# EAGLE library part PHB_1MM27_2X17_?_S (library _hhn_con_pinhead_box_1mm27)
Pin Header Box-Type, 1.27mm/0.5"/50mil Pitch, 2x17 Circuits, single gates in schematic Note: see library description for an important note about THT-version
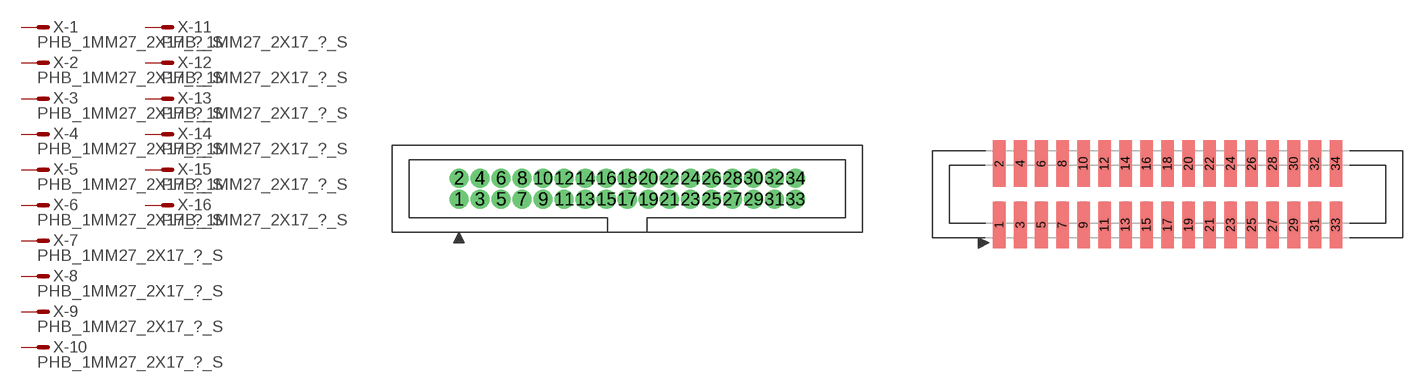
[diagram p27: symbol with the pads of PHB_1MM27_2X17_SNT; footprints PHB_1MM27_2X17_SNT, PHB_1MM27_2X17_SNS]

Designator prefix X; gates -1=M -2=M -3=M -4=M -5=M -6=M -7=M -8=M -9=M -10=M -11=M -12=M -13=M -14=M -15=M -16=M -17=M -18=M -19=M -20=M -21=M -22=M -23=M -24=M -25=M -26=M -27=M -28=M -29=M -30=M -31=M -32=M -33=M -34=M

## PHB_1MM27_2X17_SNT_S  [PHB_1MM27_2X17_SNT]
1  -1:S  pas
2  -2:S  pas
3  -3:S  pas
4  -4:S  pas
5  -5:S  pas
6  -6:S  pas
7  -7:S  pas
8  -8:S  pas
9  -9:S  pas
10  -10:S  pas
11  -11:S  pas
12  -12:S  pas
13  -13:S  pas
14  -14:S  pas
15  -15:S  pas
16  -16:S  pas
17  -17:S  pas
18  -18:S  pas
19  -19:S  pas
20  -20:S  pas
21  -21:S  pas
22  -22:S  pas
23  -23:S  pas
24  -24:S  pas
25  -25:S  pas
26  -26:S  pas
27  -27:S  pas
28  -28:S  pas
29  -29:S  pas
30  -30:S  pas
31  -31:S  pas
32  -32:S  pas
33  -33:S  pas
34  -34:S  pas

## PHB_1MM27_2X17_SNS_S  [PHB_1MM27_2X17_SNS]
Pads as for PHB_1MM27_2X17_SNT

## Footprint PHB_1MM27_2X17_SNT (pad centres in mm)
Pin Header Box-Type, 1.27mm Pitch, 2x17 circuits, Straight, No Locking, THT Important Note: Diameter in this lbr is set to a specific value (NOT 'auto' = 0), this is ignored by actual eagle versions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
drill 0.65 pad 1 round: 1 -10.16,-0.635; 2 -10.16,0.635; 3 -8.89,-0.635; 4 -8.89,0.635; 5 -7.62,-0.635; 6 -7.62,0.635; 7 -6.35,-0.635; 8 -6.35,0.635; 9 -5.08,-0.635; 10 -5.08,0.635; 11 -3.81,-0.635; 12 -3.81,0.635; 13 -2.54,-0.635; 14 -2.54,0.635; 15 -1.27,-0.635; 16 -1.27,0.635; 17 0,-0.635; 18 0,0.635; 19 1.27,-0.635; 20 1.27,0.635; 21 2.54,-0.635; 22 2.54,0.635; 23 3.81,-0.635; 24 3.81,0.635; 25 5.08,-0.635; 26 5.08,0.635; 27 6.35,-0.635; 28 6.35,0.635; 29 7.62,-0.635; 30 7.62,0.635; 31 8.89,-0.635; 32 8.89,0.635; 33 10.16,-0.635; 34 10.16,0.635

## Footprint PHB_1MM27_2X17_SNS (pad centres in mm)
Pin Header Box-Type, 1.27mm Pitch, 2x17 circuits, Straight, No Locking, SMT
smd 0.76 x 2.8: 1 -10.16,-1.85; 2 -10.16,1.85; 3 -8.89,-1.85; 4 -8.89,1.85; 5 -7.62,-1.85; 6 -7.62,1.85; 7 -6.35,-1.85; 8 -6.35,1.85; 9 -5.08,-1.85; 10 -5.08,1.85; 11 -3.81,-1.85; 12 -3.81,1.85; 13 -2.54,-1.85; 14 -2.54,1.85; 15 -1.27,-1.85; 16 -1.27,1.85; 17 0,-1.85; 18 0,1.85; 19 1.27,-1.85; 20 1.27,1.85; 21 2.54,-1.85; 22 2.54,1.85; 23 3.81,-1.85; 24 3.81,1.85; 25 5.08,-1.85; 26 5.08,1.85; 27 6.35,-1.85; 28 6.35,1.85; 29 7.62,-1.85; 30 7.62,1.85; 31 8.89,-1.85; 32 8.89,1.85; 33 10.16,-1.85; 34 10.16,1.85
